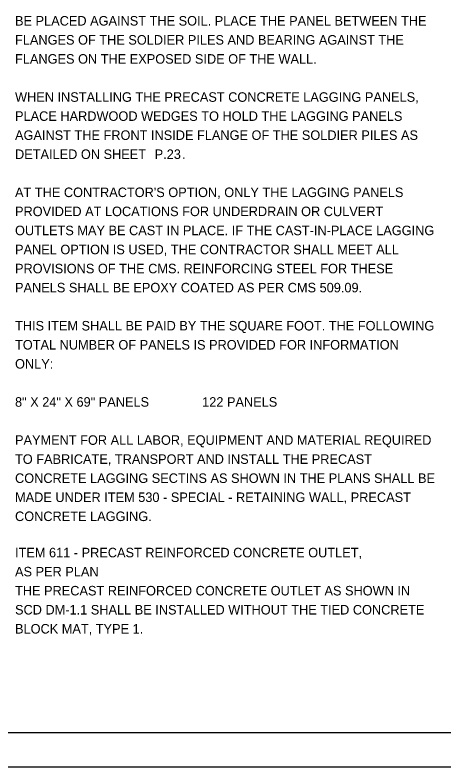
# Model space of a CAD drawing. Extents: x 0 to 34, y 0 to 22.
# Drawn here: x 17.24 to 23.54, y 0 to 11.05 of the extents above; entities that cross this region are included whole.
import ezdxf

# ---------------------------------------------------------------- set-up
doc = ezdxf.new("R2010")
doc.units = 0
for name, color, linetype in [('RD_P_Text', 7, 'Continuous'), ('SH_Border', 7, 'Continuous'), ('SH_Cut_Line', 7, 'Continuous')]:
    doc.layers.add(name, color=color, linetype=linetype)

msp = doc.modelspace()

# ---------------------------------------------------------------- linework, layer by layer
at = {"layer": 'SH_Border'}
msp.add_lwpolyline([(1.5, 21.5), (33.5, 21.5), (33.5, 0.5), (1.5, 0.5)], close=True, dxfattribs=at)
at = {"layer": 'SH_Cut_Line'}
msp.add_lwpolyline([(0, 0), (34, 0), (34, 22), (0, 22)], close=True, dxfattribs=at)

# ---------------------------------------------------------------- texts
at = {"layer": 'RD_P_Text'}
for s, p in [('BE PLACED AGAINST THE SOIL. PLACE THE PANEL BETWEEN THE ', (17.24, 10.893)), ('FLANGES OF THE SOLDIER PILES AND BEARING AGAINST THE ', (17.24, 10.613)), ('FLANGES ON THE EXPOSED SIDE OF THE WALL.', (17.24, 10.333)), ('WHEN INSTALLING THE PRECAST CONCRETE LAGGING PANELS, ', (17.24, 9.773)), ('PLACE HARDWOOD WEDGES TO HOLD THE LAGGING PANELS ', (17.24, 9.493)), ('AGAINST THE FRONT INSIDE FLANGE OF THE SOLDIER PILES AS ', (17.24, 9.213)), ('DETAILED ON SHEET ', (17.24, 8.933)), ('P.23', (19.291, 8.933)), ('.', (19.693, 8.933)), ("AT THE CONTRACTOR'S OPTION, ONLY THE LAGGING PANELS ", (17.24, 8.373)), ('PROVIDED AT LOCATIONS FOR UNDERDRAIN OR CULVERT ', (17.24, 8.093)), ('OUTLETS MAY BE CAST IN PLACE. IF THE CAST-IN-PLACE LAGGING ', (17.24, 7.813)), ('PANEL OPTION IS USED, THE CONTRACTOR SHALL MEET ALL ', (17.24, 7.533)), ('PROVISIONS OF THE CMS. REINFORCING STEEL FOR THESE ', (17.24, 7.253)), ('PANELS SHALL BE EPOXY COATED AS PER CMS 509.09.', (17.24, 6.973)), ('THIS ITEM SHALL BE PAID BY THE SQUARE FOOT. THE FOLLOWING ', (17.24, 6.413)), ('TOTAL NUMBER OF PANELS IS PROVIDED FOR INFORMATION ', (17.24, 6.133)), ('ONLY:', (17.24, 5.853)), ('8" X 24" X 69" PANELS               122 PANELS', (17.24, 5.293)), ('PAYMENT FOR ALL LABOR, EQUIPMENT AND MATERIAL REQUIRED ', (17.24, 4.733)), ('TO FABRICATE, TRANSPORT AND INSTALL THE PRECAST ', (17.24, 4.453)), ('CONCRETE LAGGING SECTINS AS SHOWN IN THE PLANS SHALL BE ', (17.24, 4.173)), ('MADE UNDER ITEM 530 - SPECIAL - RETAINING WALL, PRECAST ', (17.24, 3.893)), ('CONCRETE LAGGING.', (17.24, 3.613)), ('ITEM 611 - PRECAST REINFORCED CONCRETE OUTLET,', (17.24, 3.08)), ('AS PER PLAN', (17.24, 2.8)), ('THE PRECAST REINFORCED CONCRETE OUTLET AS SHOWN IN ', (17.24, 2.52)), ('SCD DM-1.1 SHALL BE INSTALLED WITHOUT THE TIED CONCRETE ', (17.24, 2.24)), ('BLOCK MAT, TYPE 1.', (17.24, 1.96))]:
    msp.add_text(s, height=0.14, dxfattribs=at).set_placement(p)

doc.saveas('drawing.dxf')
